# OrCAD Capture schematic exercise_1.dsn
size A
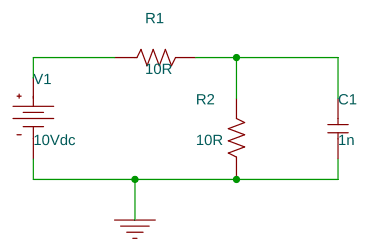
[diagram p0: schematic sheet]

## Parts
C1  1n  [cap196]
R1  10R  [AXRC05]
R2  10R  [AXRC05]
V1  VDC

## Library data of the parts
C1 = C
R1 R2 = R
V1 = VDC: DC: 10Vdc

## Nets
0: C1.1 R2.1 V1.1(-)
N00491: C1.2 R1.2 R2.2
N00560: R1.1 V1.0(+)
